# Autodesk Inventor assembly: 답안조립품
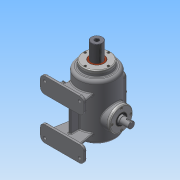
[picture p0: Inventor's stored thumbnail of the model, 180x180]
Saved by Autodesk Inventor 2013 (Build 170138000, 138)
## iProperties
Created: 2016-06
Part Number: 답안조립품
Document SubType Name: Assembly
Designer: Administrator
Author: Administrator
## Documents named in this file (15)
- C:\Users\Administrator\Desktop\Manufacturing1급-김길수\공용부품\답안조립품.iam
- C:\Users\Administrator\Desktop\Manufacturing1급-김길수\공용부품\본체.ipt
- C:\Users\Administrator\Desktop\Manufacturing1급-김길수\공용부품\슬라이드.ipt
- C:\Users\Administrator\Desktop\Manufacturing1급-김길수\공용부품\가변스프링.ipt
- C:\Users\Administrator\Desktop\Manufacturing1급-김길수\공용부품\부시.ipt
- C:\Users\Administrator\Desktop\Manufacturing1급-김길수\공용부품\슬라이드 커버.ipt
- C:\Users\Administrator\Desktop\Manufacturing1급-김길수\공용부품\볼트 M4x0.7.ipt
- C:\Users\Administrator\Desktop\Manufacturing1급-김길수\공용부품\베어링 6205.ipt
- 베어링 6205.ipt
- C:\Users\Administrator\Desktop\Manufacturing1급-김길수\공용부품\축 커버.ipt
- C:\Users\Administrator\Desktop\Manufacturing1급-김길수\공용부품\오일실.ipt
- 오일실.ipt
- C:\Users\Administrator\Desktop\Manufacturing1급-김길수\공용부품\편심축.ipt
- C:\Users\Administrator\Desktop\Manufacturing1급-김길수\공용부품\육각머리볼트 M4.ipt
- C:\Users\Administrator\Desktop\Manufacturing1급-김길수\공용부품\상부커버.ipt
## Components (13 placed, 2 different names)
1. 가변스프링:1 — 각도:6
2. M4x0.7:1
3. M4x0.7:3
4. M4x0.7:4
5. M4x0.7:5
6. M4x0.7:2
7. M4x0.7:6
8. M4x0.7:7
9. M4x0.7:8
10. M4x0.7:9
11. M4x0.7:10
12. M4x0.7:11
13. M4x0.7:12
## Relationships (1: Angle 1)
- 각도:6 [Angle]: 가변스프링:1
